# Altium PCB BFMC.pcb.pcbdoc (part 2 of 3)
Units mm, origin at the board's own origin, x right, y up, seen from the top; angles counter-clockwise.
Board outline 121.38 x 89.66 mm, 2 copper layers (Top Layer, Bottom Layer); 106 components, 51 nets, 277 pads, 97 vias.
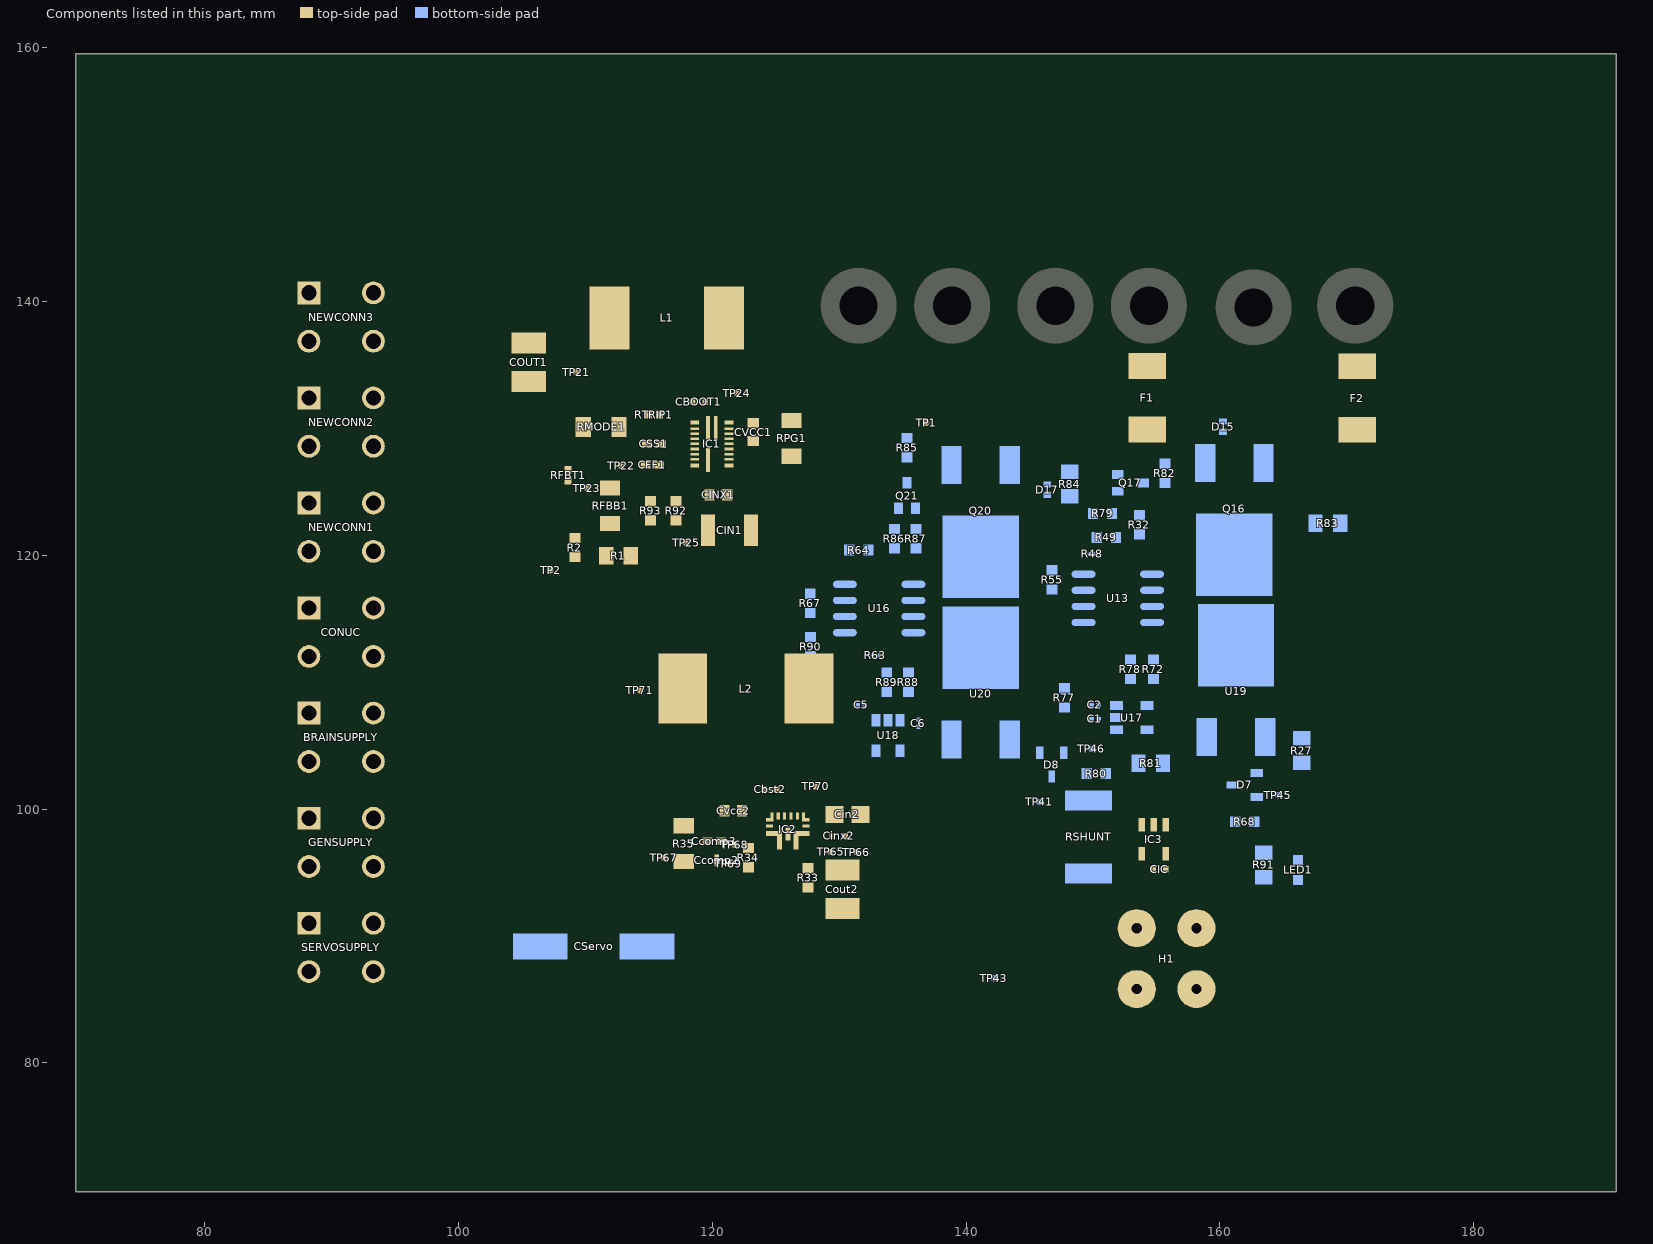
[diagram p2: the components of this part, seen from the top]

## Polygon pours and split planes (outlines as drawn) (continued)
no net on Bottom Layer (solid, remove dead copper, pour order 210): 744 vertices, not listed, extent 108.745,83.129 173.248,142.775
no net on Bottom Layer (solid, remove dead copper, pour order 212): 186 vertices, not listed, extent 87.075,84.783 144.11,115.498
no net on Bottom Layer (solid, remove dead copper, pour order 214): 480 vertices, not listed, extent 137.796,95.739 167.397,125.642
no net on Bottom Layer (solid, remove dead copper, pour order 216): 152 vertices, not listed, extent 134.66,123.807 150.34,142.902
no net on Bottom Layer (solid, remove dead copper, pour order 218): 26 vertices, not listed, extent 103.977,113.338 111.983,141.626
no net on Bottom Layer (solid, remove dead copper, pour order 220): 37 vertices, not listed, extent 87.075,87.827 111.428,94.23
no net on Bottom Layer (solid, remove dead copper, pour order 222): 22 vertices, not listed, extent 157.795,109.39 164.522,123.536
no net on Bottom Layer (solid, remove dead copper, pour order 224): 27 vertices, not listed, extent 117.445,125.589 126.158,131.445
no net on Bottom Layer (solid, remove dead copper, pour order 226): 167.398,139.646 cw(c170.654,139.646) 170.654,142.902 cw(c170.654,139.646) 173.911,139.646 cw(c170.654,139.646) 170.654,136.389 cw(c170.654,139.646)
no net on Bottom Layer (solid, remove dead copper, pour order 228): 151.142,139.646 cw(c154.398,139.646) 154.398,142.902 cw(c154.398,139.646) 157.655,139.646 cw(c154.398,139.646) 154.398,136.389 cw(c154.398,139.646)
no net on Bottom Layer (solid, remove dead copper, pour order 230): 138.904,136.389 cw(c138.904,139.646) 135.648,139.646 cw(c138.904,139.646) 138.904,142.902 cw(c138.904,139.646) 142.161,139.646 cw(c138.904,139.646)
no net on Bottom Layer (solid, remove dead copper, pour order 232): 128.436,139.646 cw(c131.538,139.646) 131.538,142.748 cw(c131.538,139.646) 134.641,139.646 cw(c131.538,139.646) 131.538,136.543 cw(c131.538,139.646)
no net on Bottom Layer (solid, remove dead copper, pour order 234): 35 vertices, not listed, extent 142.814,93.766 153.127,96.98
no net on Bottom Layer (solid, remove dead copper, pour order 236): 117.015,88.05 112.715,88.05 cw(c112.715,88.153) 112.612,88.153 112.612,90.203 cw(c112.715,90.203) 112.715,90.306 117.015,90.306 cw(c117.015,90.203) 117.117,90.203 117.117,88.153 cw(c117.015,88.153)
no net on Bottom Layer (solid, remove dead copper, pour order 238): 98.041,136.879 cw(c99.547,136.879) 99.547,138.385 cw(c99.547,136.879) 101.054,136.879 cw(c99.547,136.879) 99.547,135.372 cw(c99.547,136.879)
no net on Bottom Layer (solid, remove dead copper, pour order 240): 24 vertices, not listed, extent 162.506,93.74 166.805,95.452
no net on Bottom Layer (solid, remove dead copper, pour order 242): 87.075,131.485 87.075,133.285 cw(c87.331,133.285) 87.331,133.541 89.131,133.541 cw(c89.131,133.285) 89.388,133.285 89.388,131.485 cw(c89.131,131.485) 89.131,131.228 87.331,131.228 cw(c87.331,131.485)
no net on Bottom Layer (solid, remove dead copper, pour order 244): 87.075,123.208 87.075,125.008 cw(c87.331,125.008) 87.331,125.265 89.131,125.265 cw(c89.131,125.008) 89.388,125.008 89.388,123.208 cw(c89.131,123.208) 89.131,122.951 87.331,122.951 cw(c87.331,123.208)
no net on Bottom Layer (solid, remove dead copper, pour order 246): 87.075,139.762 87.075,141.562 cw(c87.331,141.562) 87.331,141.818 89.131,141.818 cw(c89.131,141.562) 89.388,141.562 89.388,139.762 cw(c89.131,139.762) 89.131,139.505 87.331,139.505 cw(c87.331,139.762)
no net on Bottom Layer (solid, remove dead copper, pour order 248): 89.131,114.675 87.331,114.675 cw(c87.331,114.931) 87.075,114.931 87.075,116.731 cw(c87.331,116.731) 87.331,116.988 89.131,116.988 cw(c89.131,116.731) 89.388,116.731 89.388,114.931 cw(c89.131,114.931)
no net on Bottom Layer (solid, remove dead copper, pour order 250): 92.155,124.108 cw(c93.311,124.108) 93.311,125.265 cw(c93.311,124.108) 94.468,124.108 cw(c93.311,124.108) 93.311,122.951 cw(c93.311,124.108)
no net on Bottom Layer (solid, remove dead copper, pour order 252): 92.155,132.385 cw(c93.311,132.385) 93.311,133.541 cw(c93.311,132.385) 94.468,132.385 cw(c93.311,132.385) 93.311,131.228 cw(c93.311,132.385)
no net on Bottom Layer (solid, remove dead copper, pour order 254): 92.155,140.662 cw(c93.311,140.662) 93.311,141.818 cw(c93.311,140.662) 94.468,140.662 cw(c93.311,140.662) 93.311,139.505 cw(c93.311,140.662)
no net on Bottom Layer (solid, remove dead copper, pour order 256): 87.075,98.377 87.075,100.177 cw(c87.331,100.177) 87.331,100.434 89.131,100.434 cw(c89.131,100.177) 89.388,100.177 89.388,98.377 cw(c89.131,98.377) 89.131,98.121 87.331,98.121 cw(c87.331,98.377)
no net on Bottom Layer (solid, remove dead copper, pour order 258): 92.155,95.467 cw(c93.311,95.467) 93.311,96.624 cw(c93.311,95.467) 94.468,95.467 cw(c93.311,95.467) 93.311,94.311 cw(c93.311,95.467)
no net on Bottom Layer (solid, remove dead copper, pour order 260): 92.155,115.831 cw(c93.311,115.831) 93.311,116.988 cw(c93.311,115.831) 94.468,115.831 cw(c93.311,115.831) 93.311,114.675 cw(c93.311,115.831)
no net on Bottom Layer (solid, remove dead copper, pour order 262): 87.075,95.467 cw(c88.231,95.467) 88.231,96.624 cw(c88.231,95.467) 89.388,95.467 cw(c88.231,95.467) 88.231,94.311 cw(c88.231,95.467)
no net on Bottom Layer (solid, remove dead copper, pour order 264): 93.311,98.121 cw(c93.311,99.277) 92.155,99.277 cw(c93.311,99.277) 93.311,100.434 cw(c93.311,99.277) 94.468,99.277 cw(c93.311,99.277)
no net on Bottom Layer (solid, remove dead copper, pour order 266): 88.231,127.572 cw(c88.231,128.575) 87.229,128.575 cw(c88.231,128.575) 88.231,129.577 cw(c88.231,128.575) 89.234,128.575 cw(c88.231,128.575)
no net on Bottom Layer (solid, remove dead copper, pour order 268): 93.311,127.572 cw(c93.311,128.575) 92.309,128.575 cw(c93.311,128.575) 93.311,129.577 cw(c93.311,128.575) 94.314,128.575 cw(c93.311,128.575)
no net on Bottom Layer (solid, remove dead copper, pour order 270): 88.231,119.295 cw(c88.231,120.298) 87.229,120.298 cw(c88.231,120.298) 88.231,121.301 cw(c88.231,120.298) 89.234,120.298 cw(c88.231,120.298)
no net on Bottom Layer (solid, remove dead copper, pour order 272): 93.311,135.849 cw(c93.311,136.852) 92.309,136.852 cw(c93.311,136.852) 93.311,137.854 cw(c93.311,136.852) 94.314,136.852 cw(c93.311,136.852)
no net on Bottom Layer (solid, remove dead copper, pour order 274): 88.231,135.849 cw(c88.231,136.852) 87.229,136.852 cw(c88.231,136.852) 88.231,137.854 cw(c88.231,136.852) 89.234,136.852 cw(c88.231,136.852)
no net on Bottom Layer (solid, remove dead copper, pour order 276): 92.309,120.298 cw(c93.311,120.298) 93.311,121.301 cw(c93.311,120.298) 94.314,120.298 cw(c93.311,120.298) 93.311,119.295 cw(c93.311,120.298)
no net on Bottom Layer (solid, remove dead copper, pour order 278): 93.311,86.188 cw(c93.311,87.191) 92.309,87.191 cw(c93.311,87.191) 93.311,88.193 cw(c93.311,87.191) 94.314,87.191 cw(c93.311,87.191)
no net on Bottom Layer (solid, remove dead copper, pour order 280): 88.231,102.742 cw(c88.231,103.744) 87.229,103.744 cw(c88.231,103.744) 88.231,104.747 cw(c88.231,103.744) 89.234,103.744 cw(c88.231,103.744)
no net on Bottom Layer (solid, remove dead copper, pour order 282): 88.231,86.188 cw(c88.231,87.191) 87.229,87.191 cw(c88.231,87.191) 88.231,88.193 cw(c88.231,87.191) 89.234,87.191 cw(c88.231,87.191)
no net on Bottom Layer (solid, remove dead copper, pour order 284): 93.311,102.742 cw(c93.311,103.744) 92.309,103.744 cw(c93.311,103.744) 93.311,104.747 cw(c93.311,103.744) 94.314,103.744 cw(c93.311,103.744)
no net on Bottom Layer (solid, remove dead copper, pour order 286): 167.14,102.961 165.763,102.961 cw(c165.763,103.063) 165.66,103.063 165.66,104.196 cw(c165.763,104.196) 165.763,104.298 167.14,104.298 cw(c167.14,104.196) 167.243,104.196 167.243,103.063 cw(c167.14,103.063)
no net on Bottom Layer (solid, remove dead copper, pour order 288): 154.849,102.907 154.849,104.284 cw(c154.951,104.284) 154.951,104.387 156.084,104.387 cw(c156.084,104.284) 156.186,104.284 156.186,102.907 cw(c156.084,102.907) 156.084,102.805 154.951,102.805 cw(c154.951,102.907)
no net on Bottom Layer (solid, remove dead copper, pour order 290): 162.145,100.641 162.145,101.251 cw(c162.401,101.251) 162.401,101.507 163.376,101.507 cw(c163.376,101.251) 163.633,101.251 163.633,100.641 cw(c163.376,100.641) 163.376,100.384 162.401,100.384 cw(c162.401,100.641)
no net on Bottom Layer (solid, remove dead copper, pour order 292): 129.406,117.701 cw(c129.795,117.701) 129.795,118.09 131.109,118.09 cw(c131.109,117.701) 131.499,117.701 cw(c131.109,117.701) 131.109,117.311 129.795,117.311 cw(c129.795,117.701)
no net on Bottom Layer (solid, remove dead copper, pour order 294): 154.751,105.793 153.751,105.793 cw(c153.751,105.896) 153.649,105.896 153.649,106.596 cw(c153.751,106.596) 153.751,106.698 154.751,106.698 cw(c154.751,106.596) 154.854,106.596 154.854,105.896 cw(c154.751,105.896)
no net on Bottom Layer (solid, remove dead copper, pour order 296): 154.751,107.693 153.751,107.693 cw(c153.751,107.796) 153.649,107.796 153.649,108.496 cw(c153.751,108.496) 153.751,108.598 154.751,108.598 cw(c154.751,108.496) 154.854,108.496 154.854,107.796 cw(c154.751,107.796)
no net on Bottom Layer (solid, remove dead copper, pour order 298): 135.151,103.993 134.451,103.993 cw(c134.451,104.096) 134.349,104.096 134.349,105.096 cw(c134.451,105.096) 134.451,105.198 135.151,105.198 cw(c135.151,105.096) 135.254,105.096 135.254,104.096 cw(c135.151,104.096)
no net on Bottom Layer (solid, remove dead copper, pour order 300): 132.449,104.096 132.449,105.096 cw(c132.552,105.096) 132.552,105.198 133.252,105.198 cw(c133.252,105.096) 133.354,105.096 133.354,104.096 cw(c133.252,104.096) 133.252,103.993 132.552,103.993 cw(c132.552,104.096)
no net on Bottom Layer (solid, remove dead copper, pour order 302): 155.183,109.737 154.319,109.737 cw(c154.319,109.839) 154.217,109.839 154.217,110.646 cw(c154.319,110.646) 154.319,110.748 155.183,110.748 cw(c155.183,110.646) 155.286,110.646 155.286,109.839 cw(c155.183,109.839)
no net on Bottom Layer (solid, remove dead copper, pour order 304): 128.156,116.443 127.292,116.443 cw(c127.292,116.546) 127.19,116.546 127.19,117.352 cw(c127.292,117.352) 127.292,117.455 128.156,117.455 cw(c128.156,117.352) 128.259,117.352 128.259,116.546 cw(c128.156,116.546)
no net on Bottom Layer (solid, remove dead copper, pour order 306): 146.244,118.406 146.244,119.212 cw(c146.346,119.212) 146.346,119.315 147.21,119.315 cw(c147.21,119.212) 147.313,119.212 147.313,118.406 cw(c147.21,118.406) 147.21,118.303 146.346,118.303 cw(c146.346,118.406)
no net on Bottom Layer (solid, remove dead copper, pour order 308): 135.517,120.139 135.517,120.946 cw(c135.619,120.946) 135.619,121.048 136.483,121.048 cw(c136.483,120.946) 136.586,120.946 136.586,120.139 cw(c136.483,120.139) 136.483,120.037 135.619,120.037 cw(c135.619,120.139)
no net on Bottom Layer (solid, remove dead copper, pour order 310): 149.492,122.864 149.492,123.728 cw(c149.595,123.728) 149.595,123.83 150.401,123.83 cw(c150.401,123.728) 150.504,123.728 150.504,122.864 cw(c150.401,122.864) 150.401,122.761 149.595,122.761 cw(c149.595,122.864)
no net on Bottom Layer (solid, remove dead copper, pour order 312): 166.555,95.493 165.755,95.493 cw(c165.755,95.595) 165.652,95.595 165.652,96.395 cw(c165.755,96.395) 165.755,96.498 166.555,96.498 cw(c166.555,96.395) 166.657,96.395 166.657,95.595 cw(c166.555,95.595)
no net on Bottom Layer (solid, remove dead copper, pour order 314): 152.385,125.904 151.485,125.904 cw(c151.485,126.006) 151.383,126.006 151.383,126.706 cw(c151.485,126.706) 151.485,126.809 152.385,126.809 cw(c152.385,126.706) 152.488,126.706 152.488,126.006 cw(c152.385,126.006)
no net on Bottom Layer (solid, remove dead copper, pour order 316): 135.041,123.127 134.341,123.127 cw(c134.341,123.23) 134.239,123.23 134.239,124.13 cw(c134.341,124.13) 134.341,124.232 135.041,124.232 cw(c135.041,124.13) 135.144,124.13 135.144,123.23 cw(c135.041,123.23)
no net on Bottom Layer (solid, remove dead copper, pour order 318): 83.51,82.752 cw(c83.51,82.854) 83.497,82.753 cw(c83.51,82.854) 83.408,82.854 83.408,144.137 cw(c83.51,144.137) 83.408,144.14 cw(c83.51,144.137) 83.51,144.239 174.793,144.239 cw(c174.793,144.137) 174.895,144.14 cw(c174.793,144.138) 174.895,144.137 174.895,82.854 cw(c174.793,82.854) 174.895,82.846 cw(c174.793,82.854) 174.793,82.752
no net on Bottom Layer (solid, remove dead copper, pour order 320): 744 vertices, not listed, extent 108.745,83.129 173.248,142.775
no net on Bottom Layer (solid, remove dead copper, pour order 322): 186 vertices, not listed, extent 87.075,84.783 144.11,115.498
no net on Bottom Layer (solid, remove dead copper, pour order 324): 490 vertices, not listed, extent 137.796,95.739 167.397,125.642
no net on Bottom Layer (solid, remove dead copper, pour order 326): 152 vertices, not listed, extent 134.66,123.807 150.34,142.902
no net on Bottom Layer (solid, remove dead copper, pour order 328): 26 vertices, not listed, extent 103.977,113.338 111.983,141.626
no net on Bottom Layer (solid, remove dead copper, pour order 330): 37 vertices, not listed, extent 87.075,87.827 111.428,94.23
no net on Bottom Layer (solid, remove dead copper, pour order 332): 22 vertices, not listed, extent 157.795,109.39 164.522,123.536
no net on Bottom Layer (solid, remove dead copper, pour order 334): 27 vertices, not listed, extent 117.445,125.589 126.158,131.445
no net on Bottom Layer (solid, remove dead copper, pour order 336): 170.654,136.389 cw(c170.654,139.646) 167.398,139.646 cw(c170.654,139.646) 170.654,142.902 cw(c170.654,139.646) 173.911,139.646 cw(c170.654,139.646)
no net on Bottom Layer (solid, remove dead copper, pour order 338): 151.142,139.646 cw(c154.398,139.646) 154.398,142.902 cw(c154.398,139.646) 157.655,139.646 cw(c154.398,139.646) 154.398,136.389 cw(c154.398,139.646)
no net on Bottom Layer (solid, remove dead copper, pour order 340): 135.648,139.646 cw(c138.904,139.646) 138.904,142.902 cw(c138.904,139.646) 142.161,139.646 cw(c138.904,139.646) 138.904,136.389 cw(c138.904,139.646)
no net on Bottom Layer (solid, remove dead copper, pour order 342): 131.538,136.543 cw(c131.538,139.646) 128.436,139.646 cw(c131.538,139.646) 131.538,142.748 cw(c131.538,139.646) 134.641,139.646 cw(c131.538,139.646)
no net on Bottom Layer (solid, remove dead copper, pour order 344): 35 vertices, not listed, extent 142.814,93.766 153.127,96.98
no net on Bottom Layer (solid, remove dead copper, pour order 346): 117.015,88.05 112.715,88.05 cw(c112.715,88.153) 112.612,88.153 112.612,90.203 cw(c112.715,90.203) 112.715,90.306 117.015,90.306 cw(c117.015,90.203) 117.117,90.203 117.117,88.153 cw(c117.015,88.153)
no net on Bottom Layer (solid, remove dead copper, pour order 348): 99.547,135.372 cw(c99.547,136.879) 98.041,136.879 cw(c99.547,136.879) 99.547,138.385 cw(c99.547,136.879) 101.054,136.879 cw(c99.547,136.879)
no net on Bottom Layer (solid, remove dead copper, pour order 350): 24 vertices, not listed, extent 162.506,93.74 166.805,95.452
no net on Bottom Layer (solid, remove dead copper, pour order 352): 87.075,131.485 87.075,133.285 cw(c87.331,133.285) 87.331,133.541 89.131,133.541 cw(c89.131,133.285) 89.388,133.285 89.388,131.485 cw(c89.131,131.485) 89.131,131.228 87.331,131.228 cw(c87.331,131.485)
no net on Bottom Layer (solid, remove dead copper, pour order 354): 87.075,123.208 87.075,125.008 cw(c87.331,125.008) 87.331,125.265 89.131,125.265 cw(c89.131,125.008) 89.388,125.008 89.388,123.208 cw(c89.131,123.208) 89.131,122.951 87.331,122.951 cw(c87.331,123.208)
no net on Bottom Layer (solid, remove dead copper, pour order 356): 89.131,139.505 87.331,139.505 cw(c87.331,139.762) 87.075,139.762 87.075,141.562 cw(c87.331,141.562) 87.331,141.818 89.131,141.818 cw(c89.131,141.562) 89.388,141.562 89.388,139.762 cw(c89.131,139.762)
no net on Bottom Layer (solid, remove dead copper, pour order 358): 89.131,114.675 87.331,114.675 cw(c87.331,114.931) 87.075,114.931 87.075,116.731 cw(c87.331,116.731) 87.331,116.988 89.131,116.988 cw(c89.131,116.731) 89.388,116.731 89.388,114.931 cw(c89.131,114.931)
no net on Bottom Layer (solid, remove dead copper, pour order 360): 93.311,139.505 cw(c93.311,140.662) 92.155,140.662 cw(c93.311,140.662) 93.311,141.818 cw(c93.311,140.662) 94.468,140.662 cw(c93.311,140.662)
no net on Bottom Layer (solid, remove dead copper, pour order 362): 93.311,131.228 cw(c93.311,132.385) 92.155,132.385 cw(c93.311,132.385) 93.311,133.541 cw(c93.311,132.385) 94.468,132.385 cw(c93.311,132.385)
no net on Bottom Layer (solid, remove dead copper, pour order 364): 92.155,124.108 cw(c93.311,124.108) 93.311,125.265 cw(c93.311,124.108) 94.468,124.108 cw(c93.311,124.108) 93.311,122.951 cw(c93.311,124.108)
no net on Bottom Layer (solid, remove dead copper, pour order 366): 87.075,98.377 87.075,100.177 cw(c87.331,100.177) 87.331,100.434 89.131,100.434 cw(c89.131,100.177) 89.388,100.177 89.388,98.377 cw(c89.131,98.377) 89.131,98.121 87.331,98.121 cw(c87.331,98.377)
no net on Bottom Layer (solid, remove dead copper, pour order 368): 88.231,94.311 cw(c88.231,95.467) 87.075,95.467 cw(c88.231,95.467) 88.231,96.624 cw(c88.231,95.467) 89.388,95.467 cw(c88.231,95.467)
no net on Bottom Layer (solid, remove dead copper, pour order 370): 93.311,114.675 cw(c93.311,115.831) 92.155,115.831 cw(c93.311,115.831) 93.311,116.988 cw(c93.311,115.831) 94.468,115.831 cw(c93.311,115.831)
no net on Bottom Layer (solid, remove dead copper, pour order 372): 93.311,94.311 cw(c93.311,95.467) 92.155,95.467 cw(c93.311,95.467) 93.311,96.624 cw(c93.311,95.467) 94.468,95.467 cw(c93.311,95.467)
no net on Bottom Layer (solid, remove dead copper, pour order 374): 93.311,98.121 cw(c93.311,99.277) 92.155,99.277 cw(c93.311,99.277) 93.311,100.434 cw(c93.311,99.277) 94.468,99.277 cw(c93.311,99.277)
no net on Bottom Layer (solid, remove dead copper, pour order 376): 88.231,119.295 cw(c88.231,120.298) 87.229,120.298 cw(c88.231,120.298) 88.231,121.301 cw(c88.231,120.298) 89.234,120.298 cw(c88.231,120.298)
no net on Bottom Layer (solid, remove dead copper, pour order 378): 93.311,119.295 cw(c93.311,120.298) 92.309,120.298 cw(c93.311,120.298) 93.311,121.301 cw(c93.311,120.298) 94.314,120.298 cw(c93.311,120.298)
no net on Bottom Layer (solid, remove dead copper, pour order 380): 88.231,135.849 cw(c88.231,136.852) 87.229,136.852 cw(c88.231,136.852) 88.231,137.854 cw(c88.231,136.852) 89.234,136.852 cw(c88.231,136.852)
no net on Bottom Layer (solid, remove dead copper, pour order 382): 93.311,127.572 cw(c93.311,128.575) 92.309,128.575 cw(c93.311,128.575) 93.311,129.577 cw(c93.311,128.575) 94.314,128.575 cw(c93.311,128.575)
no net on Bottom Layer (solid, remove dead copper, pour order 384): 87.229,128.575 cw(c88.231,128.575) 88.231,129.577 cw(c88.231,128.575) 89.234,128.575 cw(c88.231,128.575) 88.231,127.572 cw(c88.231,128.575)
no net on Bottom Layer (solid, remove dead copper, pour order 386): 93.311,135.849 cw(c93.311,136.852) 92.309,136.852 cw(c93.311,136.852) 93.311,137.854 cw(c93.311,136.852) 94.314,136.852 cw(c93.311,136.852)
no net on Bottom Layer (solid, remove dead copper, pour order 388): 92.309,87.191 cw(c93.311,87.191) 93.311,88.193 cw(c93.311,87.191) 94.314,87.191 cw(c93.311,87.191) 93.311,86.188 cw(c93.311,87.191)
no net on Bottom Layer (solid, remove dead copper, pour order 390): 88.231,102.742 cw(c88.231,103.744) 87.229,103.744 cw(c88.231,103.744) 88.231,104.747 cw(c88.231,103.744) 89.234,103.744 cw(c88.231,103.744)
no net on Bottom Layer (solid, remove dead copper, pour order 392): 88.231,86.188 cw(c88.231,87.191) 87.229,87.191 cw(c88.231,87.191) 88.231,88.193 cw(c88.231,87.191) 89.234,87.191 cw(c88.231,87.191)
no net on Bottom Layer (solid, remove dead copper, pour order 394): 93.311,102.742 cw(c93.311,103.744) 92.309,103.744 cw(c93.311,103.744) 93.311,104.747 cw(c93.311,103.744) 94.314,103.744 cw(c93.311,103.744)
no net on Bottom Layer (solid, remove dead copper, pour order 396): 165.66,103.063 165.66,104.196 cw(c165.763,104.196) 165.763,104.298 167.14,104.298 cw(c167.14,104.196) 167.243,104.196 167.243,103.063 cw(c167.14,103.063) 167.14,102.961 165.763,102.961 cw(c165.763,103.063)
no net on Bottom Layer (solid, remove dead copper, pour order 398): 156.084,102.805 154.951,102.805 cw(c154.951,102.907) 154.849,102.907 154.849,104.284 cw(c154.951,104.284) 154.951,104.387 156.084,104.387 cw(c156.084,104.284) 156.186,104.284 156.186,102.907 cw(c156.084,102.907)
no net on Bottom Layer (solid, remove dead copper, pour order 400): 163.376,100.384 162.401,100.384 cw(c162.401,100.641) 162.145,100.641 162.145,101.251 cw(c162.401,101.251) 162.401,101.507 163.376,101.507 cw(c163.376,101.251) 163.633,101.251 163.633,100.641 cw(c163.376,100.641)
no net on Bottom Layer (solid, remove dead copper, pour order 402): 131.109,117.311 129.795,117.311 cw(c129.795,117.701) 129.406,117.701 cw(c129.795,117.701) 129.795,118.09 131.109,118.09 cw(c131.109,117.701) 131.499,117.701 cw(c131.109,117.701)
no net on Bottom Layer (solid, remove dead copper, pour order 404): 154.751,105.793 153.751,105.793 cw(c153.751,105.896) 153.649,105.896 153.649,106.596 cw(c153.751,106.596) 153.751,106.698 154.751,106.698 cw(c154.751,106.596) 154.854,106.596 154.854,105.896 cw(c154.751,105.896)
no net on Bottom Layer (solid, remove dead copper, pour order 406): 154.751,107.693 153.751,107.693 cw(c153.751,107.796) 153.649,107.796 153.649,108.496 cw(c153.751,108.496) 153.751,108.598 154.751,108.598 cw(c154.751,108.496) 154.854,108.496 154.854,107.796 cw(c154.751,107.796)
no net on Bottom Layer (solid, remove dead copper, pour order 408): 133.252,103.993 132.552,103.993 cw(c132.552,104.096) 132.449,104.096 132.449,105.096 cw(c132.552,105.096) 132.552,105.198 133.252,105.198 cw(c133.252,105.096) 133.354,105.096 133.354,104.096 cw(c133.252,104.096)
no net on Bottom Layer (solid, remove dead copper, pour order 410): 135.151,103.993 134.451,103.993 cw(c134.451,104.096) 134.349,104.096 134.349,105.096 cw(c134.451,105.096) 134.451,105.198 135.151,105.198 cw(c135.151,105.096) 135.254,105.096 135.254,104.096 cw(c135.151,104.096)
no net on Bottom Layer (solid, remove dead copper, pour order 412): 155.183,109.737 154.319,109.737 cw(c154.319,109.839) 154.217,109.839 154.217,110.646 cw(c154.319,110.646) 154.319,110.748 155.183,110.748 cw(c155.183,110.646) 155.286,110.646 155.286,109.839 cw(c155.183,109.839)
no net on Bottom Layer (solid, remove dead copper, pour order 414): 128.156,116.443 127.292,116.443 cw(c127.292,116.546) 127.19,116.546 127.19,117.352 cw(c127.292,117.352) 127.292,117.455 128.156,117.455 cw(c128.156,117.352) 128.259,117.352 128.259,116.546 cw(c128.156,116.546)
no net on Bottom Layer (solid, remove dead copper, pour order 416): 146.244,118.406 146.244,119.212 cw(c146.346,119.212) 146.346,119.315 147.21,119.315 cw(c147.21,119.212) 147.313,119.212 147.313,118.406 cw(c147.21,118.406) 147.21,118.303 146.346,118.303 cw(c146.346,118.406)
no net on Bottom Layer (solid, remove dead copper, pour order 418): 136.483,120.037 135.619,120.037 cw(c135.619,120.139) 135.517,120.139 135.517,120.946 cw(c135.619,120.946) 135.619,121.048 136.483,121.048 cw(c136.483,120.946) 136.586,120.946 136.586,120.139 cw(c136.483,120.139)
no net on Bottom Layer (solid, remove dead copper, pour order 420): 149.492,122.864 149.492,123.728 cw(c149.595,123.728) 149.595,123.83 150.401,123.83 cw(c150.401,123.728) 150.504,123.728 150.504,122.864 cw(c150.401,122.864) 150.401,122.761 149.595,122.761 cw(c149.595,122.864)
no net on Bottom Layer (solid, remove dead copper, pour order 422): 152.385,125.904 151.485,125.904 cw(c151.485,126.006) 151.383,126.006 151.383,126.706 cw(c151.485,126.706) 151.485,126.809 152.385,126.809 cw(c152.385,126.706) 152.488,126.706 152.488,126.006 cw(c152.385,126.006)
no net on Bottom Layer (solid, remove dead copper, pour order 424): 135.041,123.127 134.341,123.127 cw(c134.341,123.23) 134.239,123.23 134.239,124.13 cw(c134.341,124.13) 134.341,124.232 135.041,124.232 cw(c135.041,124.13) 135.144,124.13 135.144,123.23 cw(c135.041,123.23)
no net on Bottom Layer (solid, remove dead copper, pour order 426): 83.51,82.752 cw(c83.51,82.854) 83.484,82.755 cw(c83.51,82.854) 83.408,82.854 83.408,144.137 83.408,144.138 cw(c83.51,144.137) 83.51,144.239 174.793,144.239 cw(c174.793,144.137) 174.895,144.138 174.895,144.137 174.895,82.854 cw(c174.793,82.854) 174.895,82.846 cw(c174.793,82.854) 174.793,82.752
no net on Bottom Layer (solid, remove dead copper, pour order 428): 744 vertices, not listed, extent 108.745,83.129 173.248,142.775
no net on Bottom Layer (solid, remove dead copper, pour order 430): 186 vertices, not listed, extent 87.075,84.783 144.11,115.498
no net on Bottom Layer (solid, remove dead copper, pour order 432): 491 vertices, not listed, extent 137.796,95.739 167.397,125.642
no net on Bottom Layer (solid, remove dead copper, pour order 434): 152 vertices, not listed, extent 134.66,123.807 150.34,142.902
no net on Bottom Layer (solid, remove dead copper, pour order 436): 26 vertices, not listed, extent 103.977,113.338 111.983,141.626
no net on Bottom Layer (solid, remove dead copper, pour order 438): 37 vertices, not listed, extent 87.075,87.827 111.428,94.23
no net on Bottom Layer (solid, remove dead copper, pour order 440): 22 vertices, not listed, extent 157.795,109.39 164.522,123.536
no net on Bottom Layer (solid, remove dead copper, pour order 442): 27 vertices, not listed, extent 117.445,125.589 126.158,131.445
no net on Bottom Layer (solid, remove dead copper, pour order 444): 170.654,136.389 cw(c170.654,139.646) 167.398,139.646 cw(c170.654,139.646) 170.654,142.902 cw(c170.654,139.646) 173.911,139.646 cw(c170.654,139.646)
no net on Bottom Layer (solid, remove dead copper, pour order 446): 151.142,139.646 cw(c154.398,139.646) 154.398,142.902 cw(c154.398,139.646) 157.655,139.646 cw(c154.398,139.646) 154.398,136.389 cw(c154.398,139.646)
no net on Bottom Layer (solid, remove dead copper, pour order 448): 138.904,136.389 cw(c138.904,139.646) 135.648,139.646 cw(c138.904,139.646) 138.904,142.902 cw(c138.904,139.646) 142.161,139.646 cw(c138.904,139.646)
no net on Bottom Layer (solid, remove dead copper, pour order 450): 128.436,139.646 cw(c131.538,139.646) 131.538,142.748 cw(c131.538,139.646) 134.641,139.646 cw(c131.538,139.646) 131.538,136.543 cw(c131.538,139.646)
no net on Bottom Layer (solid, remove dead copper, pour order 452): 35 vertices, not listed, extent 142.814,93.766 153.127,96.98
no net on Bottom Layer (solid, remove dead copper, pour order 454): 117.015,88.05 112.715,88.05 cw(c112.715,88.153) 112.612,88.153 112.612,90.203 cw(c112.715,90.203) 112.715,90.306 117.015,90.306 cw(c117.015,90.203) 117.117,90.203 117.117,88.153 cw(c117.015,88.153)
no net on Bottom Layer (solid, remove dead copper, pour order 456): 98.041,136.879 cw(c99.547,136.879) 99.547,138.385 cw(c99.547,136.879) 101.054,136.879 cw(c99.547,136.879) 99.547,135.372 cw(c99.547,136.879)
no net on Bottom Layer (solid, remove dead copper, pour order 458): 24 vertices, not listed, extent 162.506,93.74 166.805,95.452
no net on Bottom Layer (solid, remove dead copper, pour order 460): 89.131,131.228 87.331,131.228 cw(c87.331,131.485) 87.075,131.485 87.075,133.285 cw(c87.331,133.285) 87.331,133.541 89.131,133.541 cw(c89.131,133.285) 89.388,133.285 89.388,131.485 cw(c89.131,131.485)
no net on Bottom Layer (solid, remove dead copper, pour order 462): 89.131,122.951 87.331,122.951 cw(c87.331,123.208) 87.075,123.208 87.075,125.008 cw(c87.331,125.008) 87.331,125.265 89.131,125.265 cw(c89.131,125.008) 89.388,125.008 89.388,123.208 cw(c89.131,123.208)
no net on Bottom Layer (solid, remove dead copper, pour order 464): 89.131,139.505 87.331,139.505 cw(c87.331,139.762) 87.075,139.762 87.075,141.562 cw(c87.331,141.562) 87.331,141.818 89.131,141.818 cw(c89.131,141.562) 89.388,141.562 89.388,139.762 cw(c89.131,139.762)
no net on Bottom Layer (solid, remove dead copper, pour order 466): 89.131,114.675 87.331,114.675 cw(c87.331,114.931) 87.075,114.931 87.075,116.731 cw(c87.331,116.731) 87.331,116.988 89.131,116.988 cw(c89.131,116.731) 89.388,116.731 89.388,114.931 cw(c89.131,114.931)
no net on Bottom Layer (solid, remove dead copper, pour order 468): 92.155,140.662 cw(c93.311,140.662) 93.311,141.818 cw(c93.311,140.662) 94.468,140.662 cw(c93.311,140.662) 93.311,139.505 cw(c93.311,140.662)
no net on Bottom Layer (solid, remove dead copper, pour order 470): 93.311,131.228 cw(c93.311,132.385) 92.155,132.385 cw(c93.311,132.385) 93.311,133.541 cw(c93.311,132.385) 94.468,132.385 cw(c93.311,132.385)
no net on Bottom Layer (solid, remove dead copper, pour order 472): 92.155,124.108 cw(c93.311,124.108) 93.311,125.265 cw(c93.311,124.108) 94.468,124.108 cw(c93.311,124.108) 93.311,122.951 cw(c93.311,124.108)
no net on Bottom Layer (solid, remove dead copper, pour order 474): 87.075,98.377 87.075,100.177 cw(c87.331,100.177) 87.331,100.434 89.131,100.434 cw(c89.131,100.177) 89.388,100.177 89.388,98.377 cw(c89.131,98.377) 89.131,98.121 87.331,98.121 cw(c87.331,98.377)
no net on Bottom Layer (solid, remove dead copper, pour order 476): 87.075,95.467 cw(c88.231,95.467) 88.231,96.624 cw(c88.231,95.467) 89.388,95.467 cw(c88.231,95.467) 88.231,94.311 cw(c88.231,95.467)
no net on Bottom Layer (solid, remove dead copper, pour order 478): 93.311,114.675 cw(c93.311,115.831) 92.155,115.831 cw(c93.311,115.831) 93.311,116.988 cw(c93.311,115.831) 94.468,115.831 cw(c93.311,115.831)
no net on Bottom Layer (solid, remove dead copper, pour order 480): 93.311,94.311 cw(c93.311,95.467) 92.155,95.467 cw(c93.311,95.467) 93.311,96.624 cw(c93.311,95.467) 94.468,95.467 cw(c93.311,95.467)
no net on Bottom Layer (solid, remove dead copper, pour order 482): 92.155,99.277 cw(c93.311,99.277) 93.311,100.434 cw(c93.311,99.277) 94.468,99.277 cw(c93.311,99.277) 93.311,98.121 cw(c93.311,99.277)
no net on Bottom Layer (solid, remove dead copper, pour order 484): 88.231,119.295 cw(c88.231,120.298) 87.229,120.298 cw(c88.231,120.298) 88.231,121.301 cw(c88.231,120.298) 89.234,120.298 cw(c88.231,120.298)
no net on Bottom Layer (solid, remove dead copper, pour order 486): 92.309,120.298 cw(c93.311,120.298) 93.311,121.301 cw(c93.311,120.298) 94.314,120.298 cw(c93.311,120.298) 93.311,119.295 cw(c93.311,120.298)
no net on Bottom Layer (solid, remove dead copper, pour order 488): 87.229,136.852 cw(c88.231,136.852) 88.231,137.854 cw(c88.231,136.852) 89.234,136.852 cw(c88.231,136.852) 88.231,135.849 cw(c88.231,136.852)
no net on Bottom Layer (solid, remove dead copper, pour order 490): 92.309,128.575 cw(c93.311,128.575) 93.311,129.577 cw(c93.311,128.575) 94.314,128.575 cw(c93.311,128.575) 93.311,127.572 cw(c93.311,128.575)
no net on Bottom Layer (solid, remove dead copper, pour order 492): 87.229,128.575 cw(c88.231,128.575) 88.231,129.577 cw(c88.231,128.575) 89.234,128.575 cw(c88.231,128.575) 88.231,127.572 cw(c88.231,128.575)
no net on Bottom Layer (solid, remove dead copper, pour order 494): 92.309,136.852 cw(c93.311,136.852) 93.311,137.854 cw(c93.311,136.852) 94.314,136.852 cw(c93.311,136.852) 93.311,135.849 cw(c93.311,136.852)
no net on Bottom Layer (solid, remove dead copper, pour order 496): 92.309,87.191 cw(c93.311,87.191) 93.311,88.193 cw(c93.311,87.191) 94.314,87.191 cw(c93.311,87.191) 93.311,86.188 cw(c93.311,87.191)
no net on Bottom Layer (solid, remove dead copper, pour order 498): 88.231,102.742 cw(c88.231,103.744) 87.229,103.744 cw(c88.231,103.744) 88.231,104.747 cw(c88.231,103.744) 89.234,103.744 cw(c88.231,103.744)
no net on Bottom Layer (solid, remove dead copper, pour order 500): 88.231,86.188 cw(c88.231,87.191) 87.229,87.191 cw(c88.231,87.191) 88.231,88.193 cw(c88.231,87.191) 89.234,87.191 cw(c88.231,87.191)
no net on Bottom Layer (solid, remove dead copper, pour order 502): 93.311,102.742 cw(c93.311,103.744) 92.309,103.744 cw(c93.311,103.744) 93.311,104.747 cw(c93.311,103.744) 94.314,103.744 cw(c93.311,103.744)
no net on Bottom Layer (solid, remove dead copper, pour order 504): 167.14,102.961 165.763,102.961 cw(c165.763,103.063) 165.66,103.063 165.66,104.196 cw(c165.763,104.196) 165.763,104.298 167.14,104.298 cw(c167.14,104.196) 167.243,104.196 167.243,103.063 cw(c167.14,103.063)
no net on Bottom Layer (solid, remove dead copper, pour order 506): 156.084,102.805 154.951,102.805 cw(c154.951,102.907) 154.849,102.907 154.849,104.284 cw(c154.951,104.284) 154.951,104.387 156.084,104.387 cw(c156.084,104.284) 156.186,104.284 156.186,102.907 cw(c156.084,102.907)
no net on Bottom Layer (solid, remove dead copper, pour order 508): 162.145,100.641 162.145,101.251 cw(c162.401,101.251) 162.401,101.507 163.376,101.507 cw(c163.376,101.251) 163.633,101.251 163.633,100.641 cw(c163.376,100.641) 163.376,100.384 162.401,100.384 cw(c162.401,100.641)
no net on Bottom Layer (solid, remove dead copper, pour order 510): 131.109,117.311 129.795,117.311 cw(c129.795,117.701) 129.406,117.701 cw(c129.795,117.701) 129.795,118.09 131.109,118.09 cw(c131.109,117.701) 131.499,117.701 cw(c131.109,117.701)
no net on Bottom Layer (solid, remove dead copper, pour order 512): 154.751,105.793 153.751,105.793 cw(c153.751,105.896) 153.649,105.896 153.649,106.596 cw(c153.751,106.596) 153.751,106.698 154.751,106.698 cw(c154.751,106.596) 154.854,106.596 154.854,105.896 cw(c154.751,105.896)
no net on Bottom Layer (solid, remove dead copper, pour order 514): 154.751,107.693 153.751,107.693 cw(c153.751,107.796) 153.649,107.796 153.649,108.496 cw(c153.751,108.496) 153.751,108.598 154.751,108.598 cw(c154.751,108.496) 154.854,108.496 154.854,107.796 cw(c154.751,107.796)
no net on Bottom Layer (solid, remove dead copper, pour order 516): 132.449,104.096 132.449,105.096 cw(c132.552,105.096) 132.552,105.198 133.252,105.198 cw(c133.252,105.096) 133.354,105.096 133.354,104.096 cw(c133.252,104.096) 133.252,103.993 132.552,103.993 cw(c132.552,104.096)
no net on Bottom Layer (solid, remove dead copper, pour order 518): 134.349,104.096 134.349,105.096 cw(c134.451,105.096) 134.451,105.198 135.151,105.198 cw(c135.151,105.096) 135.254,105.096 135.254,104.096 cw(c135.151,104.096) 135.151,103.993 134.451,103.993 cw(c134.451,104.096)
no net on Bottom Layer (solid, remove dead copper, pour order 520): 155.183,109.737 154.319,109.737 cw(c154.319,109.839) 154.217,109.839 154.217,110.646 cw(c154.319,110.646) 154.319,110.748 155.183,110.748 cw(c155.183,110.646) 155.286,110.646 155.286,109.839 cw(c155.183,109.839)
no net on Bottom Layer (solid, remove dead copper, pour order 522): 127.19,116.546 127.19,117.352 cw(c127.292,117.352) 127.292,117.455 128.156,117.455 cw(c128.156,117.352) 128.259,117.352 128.259,116.546 cw(c128.156,116.546) 128.156,116.443 127.292,116.443 cw(c127.292,116.546)
no net on Bottom Layer (solid, remove dead copper, pour order 524): 146.244,118.406 146.244,119.212 cw(c146.346,119.212) 146.346,119.315 147.21,119.315 cw(c147.21,119.212) 147.313,119.212 147.313,118.406 cw(c147.21,118.406) 147.21,118.303 146.346,118.303 cw(c146.346,118.406)
no net on Bottom Layer (solid, remove dead copper, pour order 526): 135.517,120.139 135.517,120.946 cw(c135.619,120.946) 135.619,121.048 136.483,121.048 cw(c136.483,120.946) 136.586,120.946 136.586,120.139 cw(c136.483,120.139) 136.483,120.037 135.619,120.037 cw(c135.619,120.139)
no net on Bottom Layer (solid, remove dead copper, pour order 528): 149.492,122.864 149.492,123.728 cw(c149.595,123.728) 149.595,123.83 150.401,123.83 cw(c150.401,123.728) 150.504,123.728 150.504,122.864 cw(c150.401,122.864) 150.401,122.761 149.595,122.761 cw(c149.595,122.864)
no net on Bottom Layer (solid, remove dead copper, pour order 530): 152.385,125.904 151.485,125.904 cw(c151.485,126.006) 151.383,126.006 151.383,126.706 cw(c151.485,126.706) 151.485,126.809 152.385,126.809 cw(c152.385,126.706) 152.488,126.706 152.488,126.006 cw(c152.385,126.006)
no net on Bottom Layer (solid, remove dead copper, pour order 532): 134.239,123.23 134.239,124.13 cw(c134.341,124.13) 134.341,124.232 135.041,124.232 cw(c135.041,124.13) 135.144,124.13 135.144,123.23 cw(c135.041,123.23) 135.041,123.127 134.341,123.127 cw(c134.341,123.23)
no net on Bottom Layer (solid, remove dead copper, pour order 534): 174.895,82.846 cw(c174.793,82.854) 174.793,82.752 83.51,82.752 cw(c83.51,82.854) 83.476,82.758 cw(c83.51,82.854) 83.408,82.854 83.408,144.137 83.408,144.138 cw(c83.51,144.137) 83.51,144.239 174.793,144.239 cw(c174.793,144.137) 174.895,144.138 174.895,144.137 174.895,82.854 cw(c174.793,82.854)

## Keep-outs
Board Outline Layer:
  lines w0.254: 83.151,82.496 175.151,82.496 175.151,144.496 83.151,144.496 83.151,82.496
Multi-Layer:
  circle w0.254: c99.547,136.879 r1.25
  circle w0.254: c99.564,113.992 r1.25
  region: 117.771,126.396 122.071,126.396 122.071,131.445 117.771,131.445
  region: 123.945,96.15 127.808,96.15 127.808,100.481 123.945,100.481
